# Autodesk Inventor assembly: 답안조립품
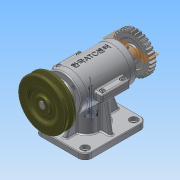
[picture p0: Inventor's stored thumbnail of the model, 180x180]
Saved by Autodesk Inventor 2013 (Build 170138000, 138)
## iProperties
Created: 2015-09
Part Number: 답안조립품
Document SubType Name: Assembly
Designer: Administrator
Mass: 2251.17 g
Surface Area: 1633.47 cm^2
Volume: 528.514 cm^3
Density: 4.25943 g/cm^3
Author: Administrator
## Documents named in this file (17)
- C:\Users\Administrator\Desktop\350908V1033\답안조립품.iam
- C:\Users\Administrator\Desktop\350908V1033\본체.ipt
- C:\Users\Administrator\Desktop\350908V1033\M3x0.5x8.ipt
- C:\Users\Administrator\Desktop\350908V1033\M4x0.5x14.ipt
- C:\Users\Administrator\Desktop\350908V1033\V-벨트풀리.ipt
- C:\Users\Administrator\Desktop\350908V1033\가변스프링.ipt
- C:\Users\Administrator\Desktop\350908V1033\뒤커버.ipt
- C:\Users\Administrator\Desktop\350908V1033\멈춤나사.ipt
- C:\Users\Administrator\Desktop\350908V1033\베어링 6201.ipt
- C:\Users\Administrator\Desktop\350908V1033\베어링 6202.ipt
- C:\Users\Administrator\Desktop\350908V1033\본체 커버.ipt
- C:\Users\Administrator\Desktop\350908V1033\스퍼기어.ipt
- C:\Users\Administrator\Desktop\350908V1033\슬라이드.ipt
- C:\Users\Administrator\Desktop\350908V1033\앞커버.ipt
- C:\Users\Administrator\Desktop\350908V1033\오일실.ipt
- C:\Users\Administrator\Desktop\350908V1033\키4x4.ipt
- C:\Users\Administrator\Desktop\350908V1033\편심축.ipt
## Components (14 placed, 4 different names)
1. V-벨트풀리:1 — 각도:1
2. 가변스프링:1
3. M4x0.5x14:1
4. M4x0.5x14:2
5. M4x0.5x14:3
6. M4x0.5x14:4
7. M3x0.5x8:2
8. M3x0.5x8:3
9. M3x0.5x8:4
10. M3x0.5x8:5
11. M3x0.5x8:1
12. M3x0.5x8:6
13. M3x0.5x8:7
14. M3x0.5x8:8
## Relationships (1: Angle 1)
- 각도:1 [Angle]: V-벨트풀리:1
